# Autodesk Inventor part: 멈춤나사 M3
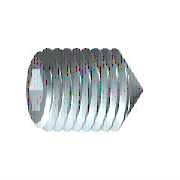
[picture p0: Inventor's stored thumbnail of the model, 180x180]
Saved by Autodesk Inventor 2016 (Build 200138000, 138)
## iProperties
IsCustomPart: 1
Created: 2012-02
Part Number: 멈춤나사 M3
Material: 강철, 연강
Description: 6각 소켓 머리 없는 멈춤 나사
Document SubType Name: Modeling
Standard: KS B 1028
Designer: test
Standards Organization: KS
Language: ko-KR
Size Designation: 원추점 M3x8
Categories: <MemberInstance><Categories><Category DisplayName="조임쇠" InternalName="e4da775c-781d-43d5-af7c-5136215cf5a6" Mnemonic="FSTN"><Category DisplayName="볼트" InternalN
Density: 7.85 g/cm^3
Appearance: 강철
Mass: 0.359881 g
Surface Area: 0.888172 cm^2
Volume: 0.0458447 cm^3
Author: test
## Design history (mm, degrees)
sketch "스케치1"
  geometry: L1 (0, 0)-(5.5, 0); L2 (8, 0.866)-(8, 1.5); L3 (8, 1.5)-(0, 1.5); L4 (8, 0.866)-(6, 0.866); L5 (6, 0.866)-(5.5, 0); L6 (0, -0.3)-(0, 1.8) reference; L7 (0, 1.5)-(0, 0)
  constraints: 13 end point, 3 parallel, 1 collinear, 1 perpendicular, 1 point on line
  dimensions: "d0" = 2 distance of L2.start L4.end (= INTI); "d1" = 60 deg angle of L5 L1; "d2" = 3 diameter of L3 L1 (= NND); "d3" = 1.73205 diameter of L4 L1 (= 1.1547 x SW); "d5" = 8 distance from line of L2 L3.end (= NLG)
revolve "본체" sketch "스케치1" stored, may be unused: angle "d6" = 90 deg
sketch "스케치2"
  geometry: L1 (-0.433, 0.75)-(0.433, 0.75); L2 (0.433, 0.75)-(0.866, 0); L3 (0.866, 0)-(0.433, -0.75); L4 (0.433, -0.75)-(-0.433, -0.75); L5 (-0.433, -0.75)-(-0.866, 0); L6 (-0.866, 0)-(-0.433, 0.75); 3 further points
  constraints: 12 end point, 1 coincident, 1 horizontal, 13 other
extrude "슬롯" join sketch "스케치2" taper "d7" = 0 deg; stored distance "d21" = 10
workaxis "Work Axis1"
workplane "Work Plane1"
sketch "스케치4"
  geometry: L1 (0, 0.15)-(-1.35, 1.5) reference; L2 (0, -0.15)-(-1.35, -1.5) reference; L3 (-1.35, -1.5)-(0.15, 0); L4 (-1.35, 1.5)-(0.15, 0); 2 further points
  constraints: 4 end point, 1 coincident, 1 collinear, 1 horizontal alignment
body "Solid1"
feature "스레드" dims "d12" = 8 (= NLG), "d13" = 0
chamfer "모따기1" distance "d8" = 1.35 (computed from NND, SPD, FAWI); stored, may be unused: angle "d9" = 45 deg (= FAWI), second distance "d34" = 1.35 (computed from NND, SPD, FAWI)
chamfer "모따기2" distance "d10" = 0.30673 (= -0.5 x GD1 + 0.5 x NND); stored, may be unused: angle "d11" = 45 deg (= FAWI), second distance "d35" = 0.30673 (= -0.5 x GD1 + 0.5 x NND)
other parameters: "NND" = 3 [user parameter; used in 5 equation terms], "NLG" = 8 [user parameter; used in 2 equation terms], "INTI" = 2 [user parameter; used in 1 equation term], "FAWI" = 45 deg [user parameter; used in 4 equation terms], "SW" = 1.5 [user parameter; used in 2 equation terms], "GD1" = 2.38655 (= THREADDIA - 1.2269 x PTC) [user parameter; used in 2 equation terms], "d4" = 0, "FAWI1" = 45 deg [user parameter], "SPD" = 0.3 [user parameter; used in 2 equation terms], "d36" = 0, "d37" = 0, "GUL" = 0.30673 (= 0.61345 x PTC) [user parameter], "TOA" = 30 deg [user parameter], "THREADDIA" = 3 [user parameter; used in 1 equation term], "PTC" = 0.5 [user parameter; used in 4 equation terms], "GAL" = 0.30673 (= 0.61345 x PTC) [user parameter], "E0" = 1.7325 (= 1.155 x SW) [user parameter]
